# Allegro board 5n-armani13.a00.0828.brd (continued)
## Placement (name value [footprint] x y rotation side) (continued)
CON5700  USB_CON_24P  [A_USB_24P_12HOLD_RA_FOX]  7.72 87 90 bottom
CON7600  WTOB_CON_7P  [TX_WTOB_7P_49_2HD_RA_ACES]  37.83 105.3 0 bottom
D1800  CH751H-40AGP  [TX_SOD323_H39]  62.43 9.98 90 bottom
D2300  1PS79SB30  [VX_SOD523_1D7]  41.17 22.38 0 top
D2400  CH751H-40AGP  [TX_SOD323_H39]  15.98 52.18 270 top
D2401  BAW56W  [TX_SOT323_PAN]  10.72 18.98 90 top
D2500  1PS79SB30  [TX_SOD523_1D7_H28]  84.25 20.35 0 top
D2600  AZ5425-01F  [TX_ESD_2P_33_39X24_H24]  13.06 77.32 90 top
D2900  AZ5425-01F  [TX_ESD_2P_33_39X24_H24]  15.14 69.88 0 top
D2901  AZ5425-01F  [TX_ESD_2P_33_39X24_H24]  15.14 66.19 0 top
D2902  1V/0.1A  [TX_SOT323]  17.68 67.85 180 top
D3000  BAT54C  [TX_SOT23_2D4_H43]  82.42 100 270 bottom
D3001  AZ5425-01F  [TX_ESD_2P_33_39X24_H24]  56.16 98.55 180 bottom
D3002  AZ5425-01F  [TX_ESD_2P_33_39X24_H24]  57.91 98.55 0 bottom
D3003  1PS79SB30  [VX_SOD523_1D7]  59.64 96.62 0 top
D3004  1PS79SB30  [VX_SOD523_1D7]  59.64 98.81 0 top
D3600  1PS79SB30  [TX_SOD523_1D7_H28]  204.62 67.34 270 bottom
D3601  AZ5725-01F  [TX_ESD_2P_33_39X24_COLAY]  134.49 18.27 0 bottom
D3602  AZ5725-01F  [TX_ESD_2P_33_39X24_COLAY]  136.77 18.27 0 bottom
D3603  AZ5725-01F  [TX_ESD_2P_33_39X24_COLAY]  140.08 18.52 0 bottom
D3604  1PS79SB30  [TX_SOD523_1D7_H28]  99.59 83.95 180 top
D3605  1PS79SB30  [TX_SOD523_1D7_H28]  59.97 23.98 0 top
D3700  CH751H-40AGP  [TX_SOD323_H39]  131.55 93.88 0 bottom
D3800  AZ5425-01F  [TX_ESD_2P_33_39X24_H24]  4.32 37.21 90 bottom
D3801  AZ5425-01F  [TX_ESD_2P_33_39X24_H24]  4.06 54 270 bottom
D3802  AZ5425-01F  [TX_ESD_2P_33_39X24_H24]  14.93 52.24 180 bottom
D3803  AZ5425-01F  [TX_ESD_2P_33_39X24_H24]  10.9 55.1 270 bottom
D3804  AZ5725-01F  [TX_ESD_2P_33_39X24_COLAY]  19.1 36.5 180 bottom
D3805  BAT54C  [TX_SOT23_2D4_H43]  49.4 13.16 270 bottom
D3806  AZ5425-01F  [TX_ESD_2P_33_39X24_H24]  15.7 39.45 0 bottom
D3807  BAT54AW  [TX_SOT323]  21.01 38.97 180 bottom
D5100  AZ5425-01F  [TX_ESD_2P_33_39X24_H24]  50.83 10.57 90 top
D5101  AZ5425-01F  [TX_ESD_2P_33_39X24_H24]  53.24 10.57 90 top
D5102  AZ5425-01F  [TX_ESD_2P_33_39X24_H24]  56.54 10.57 90 top
D5103  AZ5425-01F  [TX_ESD_2P_33_39X24_H24]  57.81 10.57 90 top
D5700  AZ5425-01F  [TX_ESD_2P_33_39X24_H24]  12.24 82.3 270 bottom
D5701  AZ5425-01F  [TX_ESD_2P_33_39X24_H24]  12.24 84.05 90 bottom
D5702  AZ5425-01F  [TX_ESD_2P_33_39X24_H24]  11.46 89.49 90 top
D5703  AZ5425-01F  [TX_ESD_2P_33_39X24_H24]  11.46 87.4 270 top
D5704  AZ5425-01F  [TX_ESD_2P_33_39X24_H24]  13.41 86.59 180 top
D5705  AZ5425-01F  [TX_ESD_2P_33_39X24_H24]  13.06 80.8 180 bottom
D5706  AZ5425-01F  [TX_ESD_2P_33_39X24_H24]  13.06 79.43 180 bottom
D5707  AZ5425-01F  [TX_ESD_2P_33_39X24_H24]  11.4 92.2 270 top
D5708  ESD5401N-2/TR  [TX_DFN1006_2P_43X28_WIL]  12.32 90.85 0 bottom
D5709  ESD5401N-2/TR  [TX_DFN1006_2P_43X28_WIL]  12.32 89.22 0 bottom
D5800  BAT54C  [TX_SOT23_2D4_H43]  19.96 75.24 270 bottom
F2600  0.75A/6V  [TX_POLYSWITCH_2P_87X59]  19.15 73.15 0 top
F3000  1.5A/24V  [TX_POLYSWITCH_2P_1812_H71]  76.66 104.22 90 bottom
F5100  0.5A/6V  [TX_POLYSWITCH_0603_71X39]  175.51 19.76 0 bottom
H5200  O118X98DO118X98N  [HOLE_O118X98DO118X98N]  217.33 24.8 0 top
H5201  CT236CB173D157  [NB_H_CT236CB173D157_P2_S]  99.93 71.05 0 top
H5202  CT236CB173D157  [NB_H_CT236CB173D157_P2_S]  99.93 37.05 0 top
H5203  C98D98N  [A_HOLE_C98D98N]  6.83 24.8 180 top
H5204  S232D87  [NB_H_S232D87_P2_S]  7.68 76.85 0 top
H5205  CT236CB173D157  [NB_H_CT236CB173D157_P2_S]  133.93 37.05 0 top
H5207  C315D169  [NB_H_C315D169_P2_S]  208.63 13.3 180 bottom
H5208  C315D169  [NB_H_C315D169_P2_S]  168.43 33.6 0 top
H5209  ST252CB315D205  [NB_H_ST252CB315D205_P2_S]  6.83 32.1 0 top
H5210  CT236CB173D157  [NB_H_CT236CB173D157_P2_S]  179.53 108.7 90 top
H5211  C315D169  [NB_H_C315D169_P2_S]  98.88 7 180 bottom
H5212  CT236CB173D157  [NB_H_CT236CB173D157_P2_S]  171.43 65.3 0 top
H5213  CT236CB173D157  [NB_H_CT236CB173D157_P2_S]  137.23 93.3 0 top
H5214  ST295CB315D169  [NB_H_ST295CB315D169_P2_S]  122.93 95.2 0 top
H5215  S209D98  [NB_H_S209D98_P2_S]  5.68 97.2 180 bottom
H5216  CT236CB173D157  [NB_H_CT236CB173D157_P2_S]  133.93 71.05 0 top
J3800  AUDIO_JACK_6P  [TX_AUDIO_JACK_6P_TECHK]  0.98 47.4 90 bottom
J5300  FPC_CON_12P  [TX_FPC_12P_20_2HD_RA_PANA]  89 4.54 0 top
J5301  FPC_CON_12P  [TX_FPC_12P_20_2HD_RA_PANA]  44.1 63.32 90 top
L2600  90ohm  [TX_CHOKE_4P_49X39_MURA]  16.82 64.65 0 bottom
L2601  90ohm  [TX_CHOKE_4P_49X39_MURA]  16.79 62.54 0 bottom
L2602  90ohm  [TX_CHOKE_4P_49X39_MURA]  16.79 60.23 0 bottom
L2603  90ohm  [TX_CHOKE_4P_49X39_MURA]  16.79 66.93 0 bottom
L3000  90ohm  [CHOKE_4P_49X39_MURA]  53.34 98.53 180 bottom
L3601  70Ohm/100Mhz  [TX_L0603_T015]  129.11 18.85 270 bottom
L3602  70Ohm/100Mhz  [TX_L0603_T015]  130.74 18.87 270 bottom
L3603  70Ohm/100Mhz  [TX_L0603_T015]  132.46 18.87 270 bottom
L3800  70Ohm/100Mhz  [TX_L0603_T015]  19.19 22.07 180 top
L3801  11Ohm/100Mhz  [TX_L0603_T02_H37]  14.13 47.94 90 bottom
L3802  11Ohm/100Mhz  [TX_L0603_T02_H37]  6.83 53.69 180 bottom
L3803  11Ohm/100Mhz  [TX_L0603_T02_H37]  13.53 53.71 180 bottom
L3804  11Ohm/100Mhz  [TX_L0603_T02_H37]  5.93 40.82 180 bottom
L3805  70Ohm/100Mhz  [TX_L0603_T015]  20.45 36.25 180 top
L3806  70Ohm/100Mhz  [TX_L0603_T015]  15.58 37.35 180 bottom
L5700  90ohm  [TX_CHOKE_4P_49X39_MURA]  14.63 83.04 90 bottom
L5701  90ohm  [TX_CHOKE_4P_49X39_MURA]  13.51 88.27 180 top
L5702  90ohm  [TX_CHOKE_4P_49X39_MURA]  17.83 85.47 0 top
L5703  90ohm  [TX_CHOKE_4P_49X39_MURA]  17.37 78.74 0 top
L5704  90ohm  [TX_CHOKE_4P_49X39_MURA]  18.29 83.34 0 top
L5705  90ohm  [TX_CHOKE_4P_49X39_MURA]  21.79 81.46 0 top
L6700  120ohm  [TX_L0402_T02]  150.07 90.58 180 top
L6701  120ohm  [TX_L0402_T02]  155.63 107.79 270 top
L6702  220Ohm  [TX_L0402]  168.88 82.55 180 top
LED5000  WHITE/YELLOW  [TX_LED_3P_126X59_CO]  1.25 99.01 90 bottom
NOREF  -  []  57.53 26.82 90 top
NOREF#2  -  []  198.96 58.41 90 top
NOREF#3  -  []  78.18 92.75 90 top
NOREF#4  -  []  2.55 55.6 90 top
NOREF#5  -  []  1.31 53.83 90 top
NOREF#6  -  [unnamed#2]  204.29 101.22 0 top
NOREF#7  -  []  53.43 25.55 90 top
NOREF#8  -  []  1.31 55.27 0 top
NOREF#9  -  []  1.25 97.51 90 top
NOREF#10  -  []  62.99 -27.18 0 top
NOREF#11  -  []  194.06 46.89 0 top
NOREF#12  -  []  62.08 25.57 90 top
NOREF#13  -  []  199.9 57.86 0 top
NOREF#14  -  []  76.13 40.3 0 top
NOREF#15  -  []  62.08 56.57 90 top
NOREF#16  -  [unnamed#2]  26.09 9.58 0 top
NOREF#17  -  []  53.43 25.55 90 top
NOREF#18  -  []  66.18 24.55 90 top
NOREF#19  -  []  53.43 25.55 90 top
NOREF#20  -  []  83.05 39.34 0 top
NOREF#21  -  [unnamed#2]  204.76 21.72 0 top
NOREF#22  -  []  220.27 77.35 270 top
NOREF#23  -  []  198.96 58.41 0 top
NOREF#24  -  []  198.75 57.66 0 top
NOREF#25  -  []  78.18 25.15 90 top
NOREF#26  -  []  198.75 57.66 90 top
NOREF#27  -  []  1.25 55.6 0 top
NOREF#28  -  [unnamed#2]  203.58 102.36 180 bottom
NOREF#29  -  []  275.44 53.76 180 bottom
NOREF#30  -  []  90.2 84.72 0 bottom
NOREF#31  -  [unnamed#2]  212.52 22.48 180 bottom
NOREF#32  -  [unnamed#2]  33.93 5.87 180 bottom
PC7600  0.1uF/50V  [TX_C0402_H22]  57.68 109.07 90 top
PC7601  1UF/50V  [TX_C0603]  43.49 100.13 180 bottom
PC7602  100PF/50V  [TX_C0402]  55.47 109.12 90 top
PC7603  0.022UF/16V  [TX_C0402]  35.59 89.51 90 top
PC7604  0.1UF/16V  [TX_C0402]  68.86 97.59 270 top
PC7605  10UF/25V  [TX_C0805_T02_H57]  30.61 97.74 90 bottom
PC7606  0.1UF/50V  [TX_C0603_T015_H37]  58.83 109.07 90 top
PC7607  0.1UF/50V  [TX_C0603_T015_H37]  40.95 100.03 180 top
PC7608  100PF/50V  [TX_C0402]  20.14 57.69 180 bottom
PC7609  1UF/50V  [TX_C0603]  30.38 100.84 180 top
PC7610  100PF/50V  [TX_C0402]  38.25 101.85 0 top
PC7611  0.1UF/50V  [TX_C0603_T015_H37]  36.51 97.48 0 top
PC7612  0.1UF/50V  [TX_C0603_T015_H37]  37.29 99.29 270 top
PC7700  10UF/25V  [TX_C0805_T02_H57]  187.73 23.9 0 bottom
PC7701  10UF/25V  [TX_C0805_T02_H57]  187.73 27.47 0 bottom
PC7702  10UF/25V  [TX_C0805_T02_H57]  187.73 25.68 0 bottom
PC7703  10UF/25V  [TX_C0805_T02_H57]  187.73 22.11 0 bottom
PC7704  10UF/25V  [TX_C0805_T02_H57]  160.88 28.15 270 bottom
PC7705  10UF/25V  [TX_C0805_T02_H57]  162.71 32.79 90 bottom
PC7706  10UF/25V  [TX_C0805_T02_H57]  159.06 28.27 270 bottom
PC7707  10UF/25V  [TX_C0805_T02_H57]  156.64 26.75 270 bottom
PC7708  4.7UF/6.3V  [TX_C0402_T02_H26]  192.28 26.9 90 bottom
PC7709  1UF/25V  [TX_C0603_T015_H37]  190.5 27.62 90 bottom
PC7710  1UF/25V  [TX_C0603_T015_H37]  190.39 25.35 270 bottom
PC7711  0.22UF/25V  [TX_C0603]  192.41 24.95 90 bottom
PC7712  1UF/25V  [TX_C0603_T015_H37]  192.71 29.34 180 bottom
PC7713  4.7UF/6.3V  [TX_C0402_T02_H26]  194.36 29.49 90 bottom
PC7714  4.7UF/6.3V  [TX_C0402_T02_H26]  192.62 22.18 270 bottom
PC7715  0.22UF/25V  [TX_C0603]  194.6 22.26 180 bottom
PC7716  0.1UF/25V  [TX_C0402]  195.35 29.49 90 bottom
PC7717  1UF/25V  [TX_C0603_T015_H37]  200.81 21.41 0 bottom
PC7718  1UF/6.3V  [TX_C0402]  198.72 22.35 90 bottom
PC7719  0.22UF/25V  [TX_C0603]  200.81 22.71 0 bottom
PC7720  10UF/25V  [TX_C0805_T02_H57]  154 24.16 0 bottom
PC7721  10PF/50V  [TX_C0402]  200.71 29.36 0 bottom
PC7722  4700PF/50V  [TX_C0402]  150.18 23.32 270 bottom
PC7723  22nF/50V  [TX_C0402]  202.36 26.37 0 bottom
PC7800  0.022UF/16V  [TX_C0402]  176.54 53.83 180 bottom
PC7801  1UF/16V  [TX_C0402]  170.33 48.57 180 bottom
PC7802  4.7UF/10V  [TX_C0603]  168.05 48.63 90 bottom
PC7803  0.1UF/16V  [TX_C0402]  176.53 54.75 0 bottom
PC7804  0.22UF/25V  [TX_C0603]  170.33 47.12 0 bottom
PC7805  2200PF/50V  [TX_C0402]  176.72 52.78 0 bottom
PC7806  0.1UF/16V  [TX_C0402]  178.59 54.66 180 bottom
PC7807  0.022UF/16V  [TX_C0402]  177.55 53.18 90 top
PC7808  0.022UF/16V  [TX_C0402]  176.61 53.14 90 top
PC7809  0.068UF/16V  [TX_C0402]  180.11 46.66 0 top
PC7810  0.027UF/25V  [TX_C0402_H22]  180.11 47.6 0 top
PC7811  2200PF/50V  [TX_C0402]  179.1 44.6 270 top
PC7812  33PF/50V  [TX_C0402]  173.25 53.32 270 bottom
PC7813  0.1UF/16V  [TX_C0402]  179.1 42.95 270 top
PC7814  68PF/50V  [TX_C0402]  179.35 49.38 0 bottom
PC7815  2200PF/50V  [TX_C0402]  173.47 57.13 180 bottom
PC7816  6800PF/25V  [TX_C0402]  181.1 50.29 180 bottom
PC7817  220PF/50V  [TX_C0402]  176.15 59.21 180 bottom
PC7818  1000PF/50V  [TX_C0402]  178.77 47.35 90 bottom
PC7819  1000PF/50V  [TX_C0402]  174.98 55.48 270 top
PC7820  330PF/50V  [TX_C0402]  174.75 55.58 90 bottom
PC7821  1000PF/50V  [TX_C0402]  180.19 50.07 180 top
PC7822  680PF/50V  [TX_C0402]  181.43 48.88 90 bottom
PC7823  10NF/25V  [TX_C0402]  175.26 53.33 90 bottom
PC7824  330PF/50V  [TX_C0402]  172.29 53.95 180 top
PC7825  330PF/50V  [TX_C0402]  176.71 49.76 0 top
PC7826  10NF/25V  [TX_C0402]  180.11 48.54 0 top
PC7827  0.047UF/16V  [TX_C0402]  167.22 46.28 90 top
PC7828  0.012UF/25V  [TX_C0402_H22]  168.15 46.28 90 top
PC7829  0.1UF/16V  [TX_C0402]  165 46.48 180 top
PC7830  2200PF/50V  [TX_C0402]  171.81 44.17 270 top
PC7831  33PF/50V  [TX_C0402]  175.95 44.6 270 bottom
PC7832  6800PF/25V  [TX_C0402]  177.75 42.55 0 top
PC7833  1000PF/50V  [TX_C0402]  170.87 44.33 90 bottom
PC7834  1000PF/50V  [TX_C0402]  175.03 44.6 270 bottom
PC7835  330PF/50V  [TX_C0402]  177.32 44.6 90 bottom
PC7836  0.1UF/16V  [TX_C0402]  167.97 49.46 0 top
PC7837  10NF/25V  [TX_C0402]  172.75 43.97 270 bottom
PC7838  100PF/50V  [TX_C0402]  173.63 42.7 180 bottom
PC7839  22nF/50V  [TX_C0402]  178.82 56.54 270 bottom
PC7840  0.068UF/16V  [TX_C0402]  177.88 56.54 270 bottom
PC7841  330PF/50V  [TX_C0402]  174.85 57.67 270 bottom
PC7900  4.7UF/10V  [TX_C0402_T02_H26]  159.03 41.91 180 bottom
PC7901  10UF/25V  [TX_C0805_T02_H57]  153.32 44.2 180 bottom
PC7902  10UF/25V  [TX_C0805_T02_H57]  153.32 42.42 180 bottom
PC7903  1000PF/50V  [TX_C0402]  156.34 49.3 270 bottom
PC7904  0.22UF/25V  [TX_C0603]  157.79 45.19 270 bottom
PC7905  1000PF/50V  [TX_C0402]  149.51 44.4 0 bottom
PC7906  10UF/25V  [TX_C0805_T02_H57]  156.31 53.04 90 bottom
PC7907  10UF/25V  [TX_C0805_T02_H57]  152.32 58.37 180 bottom
PC7908  10UF/25V  [TX_C0805_T02_H57]  152.32 56.57 180 bottom
PC7909  4.7UF/10V  [TX_C0402_T02_H26]  161.27 52.15 0 bottom
PC7910  1000PF/50V  [TX_C0402]  156.47 63.07 270 bottom
PC7911  0.22UF/25V  [TX_C0603]  157.84 54.74 270 bottom
PC7912  1000PF/50V  [TX_C0402]  149.96 58.73 0 bottom
PC7913  10UF/25V  [TX_C0805_T02_H57]  156.46 43.16 0 bottom
PC7914  1000PF/50V  [TX_C0402]  150.88 49.81 0 top
PC7915  1000PF/50V  [TX_C0402]  148.41 64.11 0 top
PC8000  0.22UF/25V  [TX_C0603]  147.75 31.75 180 bottom
PC8001  10UF/25V  [TX_C0805_T02_H57]  156.36 35.74 180 bottom
PC8002  4.7UF/10V  [TX_C0402_T02_H26]  142.98 28.73 180 bottom
PC8003  10UF/25V  [TX_C0805_T02_H57]  156.36 37.54 180 bottom
PC8004  1000PF/50V  [TX_C0402]  149.66 39.12 180 top
PC8005  1000PF/50V  [TX_C0402]  152.1 34.62 0 bottom
PC8006  4.7UF/10V  [TX_C0402_T02_H26]  161.82 62.33 0 bottom
PC8007  10UF/25V  [TX_C0805_T02_H57]  156.44 66.47 0 bottom
PC8008  10UF/25V  [TX_C0805_T02_H57]  152.81 67.87 180 bottom
PC8009  10UF/25V  [TX_C0805_T02_H57]  152.81 66.09 180 bottom
PC8010  1000PF/50V  [TX_C0402]  155.91 73.36 270 bottom
PC8011  0.22UF/25V  [TX_C0603]  158.51 65.1 270 bottom
PC8012  1000PF/50V  [TX_C0402]  148.92 71.55 0 top
PC8013  1000PF/50V  [TX_C0402]  149.89 72.8 0 top
PC8100  22UF/6.3V  [TX_C0603_T02_H39]  122.81 57.48 90 top
PC8101  22UF/6.3V  [TX_C0603_T02_H39]  115.47 57.55 90 top
PC8102  22UF/6.3V  [TX_C0603_T02_H39]  126.49 56.54 270 top
PC8103  22UF/6.3V  [TX_C0603_T02_H39]  126.67 58.87 90 top
PC8104  22UF/6.3V  [TX_C0603_T02_H39]  116.82 57.55 90 top
PC8105  22UF/6.3V  [TX_C0603_T02_H39]  138.63 55.76 270 bottom
PC8106  22UF/6.3V  [TX_C0603_T02_H39]  138.63 43.89 270 bottom
PC8107  22UF/6.3V  [TX_C0603_T02_H39]  119.04 54.89 270 top
PC8108  22UF/6.3V  [TX_C0603_T02_H39]  117.68 54.89 270 top
PC8109  22UF/6.3V  [TX_C0603_T02_H39]  116.28 54.89 270 top
PC8110  22UF/6.3V  [TX_C0603_T02_H39]  114.95 54.89 270 top
PC8111  22UF/6.3V  [TX_C0603_T02_H39]  143.79 36.96 0 top
PC8112  22UF/6.3V  [TX_C0603_T02_H39]  143.79 35.59 0 top
PC8113  22UF/6.3V  [TX_C0603_T02_H39]  143.66 34.19 0 top
PC8114  22UF/6.3V  [TX_C0603_T02_H39]  141.45 34.39 270 top
PC8115  22UF/6.3V  [TX_C0603_T02_H39]  143.79 38.31 0 top
PC8116  22UF/6.3V  [TX_C0603_T02_H39]  143.43 40.13 90 top
PC8117  22UF/6.3V  [TX_C0603_T02_H39]  142.04 40.41 90 top
PC8118  22UF/6.3V  [TX_C0603_T02_H39]  127.82 56.54 270 top
PC8119  22UF/6.3V  [TX_C0603_T02_H39]  117.58 52.22 90 top
PC8120  22UF/6.3V  [TX_C0603_T02_H39]  116.23 52.22 90 top
PC8121  22UF/6.3V  [TX_C0603_T02_H39]  114.89 52.22 90 top
PC8122  22UF/6.3V  [TX_C0603_T02_H39]  126.57 54.26 270 top
PC8123  22UF/6.3V  [TX_C0603_T02_H39]  138.79 65.33 90 bottom
PC8124  22UF/6.3V  [TX_C0603_T02_H39]  118.93 52.22 90 top
PC8125  22UF/6.3V  [TX_C0603_T02_H39]  116.26 49.56 270 top
PC8126  22UF/6.3V  [TX_C0603_T02_H39]  120.25 49.56 270 top
PC8127  22UF/6.3V  [TX_C0603_T02_H39]  118.93 49.56 270 top
PC8128  22UF/6.3V  [TX_C0603_T02_H39]  143.72 43.36 0 top
PC8129  22UF/6.3V  [TX_C0603_T02_H39]  114.91 49.56 270 top
PC8130  22UF/6.3V  [TX_C0603_T02_H39]  141.92 43.11 270 top
PC8131  22UF/6.3V  [TX_C0603_T02_H39]  140.6 43.11 270 top
PC8132  22UF/6.3V  [TX_C0603_T02_H39]  143.97 44.73 0 top
PC8133  22UF/6.3V  [TX_C0603_T02_H39]  117.59 49.56 270 top
PC8134  22UF/6.3V  [TX_C0603_T02_H39]  113.59 49.56 270 top
PC8135  22UF/6.3V  [TX_C0603_T02_H39]  118.16 57.55 90 top
PC8136  22UF/6.3V  [TX_C0603_T02_H39]  143.97 46.08 0 top
PC8137  22UF/6.3V  [TX_C0603_T02_H39]  118.21 63.4 90 top
PC8138  22UF/6.3V  [TX_C0603_T02_H39]  116.87 63.4 90 top
PC8139  22UF/6.3V  [TX_C0603_T02_H39]  115.52 63.4 90 top
PC8140  22UF/6.3V  [TX_C0603_T02_H39]  115.57 83.7 180 bottom
PC8141  22UF/6.3V  [TX_C0603_T02_H39]  124.08 77.5 0 top
PC8142  22UF/6.3V  [TX_C0603_T02_H39]  118.21 60.16 270 top
PC8143  22UF/6.3V  [TX_C0603_T02_H39]  115.47 60.16 270 top
PC8144  22UF/6.3V  [TX_C0603_T02_H39]  114.18 63.4 90 top
PC8145  22UF/6.3V  [TX_C0603_T02_H39]  111.54 64.19 180 top
PC8146  22UF/6.3V  [TX_C0603_T02_H39]  111.53 62.33 180 top
PC8147  22UF/6.3V  [TX_C0603_T02_H39]  127.58 80.22 270 bottom
PC8148  22UF/6.3V  [TX_C0603_T02_H39]  121.29 78.84 180 bottom
PC8149  22UF/6.3V  [TX_C0603_T02_H39]  124.08 77.5 0 bottom
PC8150  22UF/6.3V  [TX_C0603_T02_H39]  116.87 60.16 270 top
PC8151  22UF/6.3V  [TX_C0603_T02_H39]  128.96 80.22 270 bottom
PC8152  22UF/6.3V  [TX_C0603_T02_H39]  121.62 84.86 90 bottom
PC8153  22UF/6.3V  [TX_C0603_T02_H39]  114.12 60.16 270 top
PC8154  22UF/6.3V  [TX_C0603_T02_H39]  111.32 60.96 180 top
PC8155  22UF/6.3V  [TX_C0603_T02_H39]  111.73 79.96 0 top
PC8156  22UF/6.3V  [TX_C0603_T02_H39]  124.05 80.27 0 bottom
PC8157  22UF/6.3V  [TX_C0603_T02_H39]  120.48 46.94 90 top
PC8158  22UF/6.3V  [TX_C0603_T02_H39]  127.03 50 90 top
PC8159  22UF/6.3V  [TX_C0603_T02_H39]  119.08 46.94 90 top
PC8160  22UF/6.3V  [TX_C0603_T02_H39]  128.4 50 90 top
PC8161  22UF/6.3V  [TX_C0603_T02_H39]  140.08 34.78 270 top
PC8162  22UF/6.3V  [TX_C0603_T02_H39]  140.39 34.78 270 bottom
PC8163  22UF/6.3V  [TX_C0603_T02_H39]  121.29 80.22 180 top
PC8164  22UF/6.3V  [TX_C0603_T02_H39]  115.55 85.09 180 bottom
PC8165  22UF/6.3V  [TX_C0603_T02_H39]  111.76 81.31 0 top
PC8166  22UF/6.3V  [TX_C0603_T02_H39]  121.29 80.22 180 bottom
PC8167  22UF/6.3V  [TX_C0603_T02_H39]  126.16 80.22 270 bottom
PC8168  22UF/6.3V  [TX_C0603_T02_H39]  119.02 87.25 90 top
PC8169  22UF/6.3V  [TX_C0603_T02_H39]  124.08 80.27 0 top
PC8170  22UF/6.3V  [TX_C0603_T02_H39]  124.56 87.25 90 top
PC8171  22UF/6.3V  [TX_C0603_T02_H39]  123.19 87.25 90 top
PC8172  22UF/6.3V  [TX_C0603_T02_H39]  121.29 77.5 180 top
PC8173  22UF/6.3V  [TX_C0603_T02_H39]  129.82 87.25 90 top
PC8174  22UF/6.3V  [TX_C0603_T02_H39]  128.42 87.25 90 top
PC8175  22UF/6.3V  [TX_C0603_T02_H39]  121.29 78.84 180 top
PC8176  22UF/6.3V  [TX_C0603_T02_H39]  121.29 77.5 180 bottom
PC8177  22UF/6.3V  [TX_C0603_T02_H39]  124.08 78.89 0 bottom
PC8178  22UF/6.3V  [TX_C0603_T02_H39]  139.27 43.11 270 top
PC8179  22UF/6.3V  [TX_C0603_T02_H39]  114.12 57.55 90 top
PC8180  22UF/6.3V  [TX_C0603_T02_H39]  144.78 47.42 0 top
PC8181  22UF/6.3V  [TX_C0603_T02_H39]  144.78 48.82 0 top
PC8182  22UF/6.3V  [TX_C0603_T02_H39]  144.78 50.22 0 top
PC8183  22UF/6.3V  [TX_C0603_T02_H39]  124.08 78.89 0 top
PC8184  22UF/6.3V  [TX_C0603_T02_H39]  115.57 82.3 180 bottom
PC8185  22UF/6.3V  [TX_C0603_T02_H39]  120.42 87.25 90 top
PC8186  22UF/6.3V  [TX_C0603_T02_H39]  121.82 87.25 90 top
PC8187  22UF/6.3V  [TX_C0603_T02_H39]  119.13 84.86 90 bottom
PC8600  1UF/16V  [TX_C0402]  101.12 100.99 90 top
PC8601  0.1UF/25V  [TX_C0402]  97.13 99.34 180 top
PC8602  10UF/25V  [TX_C0805_T02_H57]  82.42 104.27 0 bottom
PC8603  10UF/25V  [TX_C0805_T02_H57]  82.42 102.49 0 bottom
PC8604  330PF/50V  [TX_C0402]  83.06 104.47 0 top
PC8605  1000PF/50V  [TX_C0402]  103.84 96.24 270 top
PC8606  1000PF/50V  [TX_C0402]  83.69 111.1 180 bottom
PC8607  680PF/50V  [TX_C0402]  83.69 110.16 180 bottom
PC8608  10UF/6.3V  [TX_C0402_T02_H28]  93.19 108.64 90 bottom
PC8609  1UF/6.3V  [TX_C0402]  104.29 99.49 0 top
PC8610  330PF/50V  [TX_C0402]  82.4 108.77 180 top
PC8611  56PF/50V  [TX_C0402]  102.87 94.41 90 top
PC8612  0.1UF/16V  [TX_C0402]  104.17 94.06 0 top
PC8613  10UF/6.3V  [TX_C0402_T02_H28]  96.32 95.71 180 top
PC8614  10UF/6.3V  [TX_C0402_T02_H28]  97.94 95.15 180 top
PC8615  10UF/6.3V  [TX_C0402_T02_H28]  97.94 94.13 180 top
PC8616  0.033UF/16V  [TX_C0402]  100.84 94.03 270 top
PC8617  22UF/6.3V  [TX_C0603_T02_H39]  98.3 97.49 0 bottom
PC8618  22UF/6.3V  [TX_C0603_T02_H39]  98.91 103.01 0 bottom
PC8619  22UF/6.3V  [TX_C0603_T02_H39]  98.29 100.26 0 bottom
PC8620  22UF/6.3V  [TX_C0603_T02_H39]  98.91 101.64 0 bottom
PC8621  1500PF/50V  [TX_C0402]  107.65 98.02 90 top
PC8622  10PF/50V  [TX_C0402]  80.14 103.89 0 bottom
PC8700  10UF/25V  [TX_C0805_T02_H57]  178.23 35.28 270 bottom
PC8701  22UF/6.3V  [TX_C0603_T02_H39]  174.27 31.45 270 bottom
PC8702  22UF/6.3V  [TX_C0603_T02_H39]  163.86 45.87 180 bottom
PC8703  22UF/6.3V  [TX_C0603_T02_H39]  163.86 47.22 180 bottom
PC8704  220PF/50V  [TX_C0402]  174.14 29.47 0 bottom
PC8705  1UF/16V  [TX_C0402]  176.35 33.12 270 bottom
PC8706  1500PF/50V  [TX_C0402]  172.36 38.67 270 bottom
PC8707  22UF/6.3V  [TX_C0603_T02_H39]  162.05 50.47 270 bottom
PC8708  22UF/6.3V  [TX_C0603_T02_H39]  166.17 46.21 0 bottom
PC8709  0.22UF/25V  [TX_C0603]  170.54 40.82 90 bottom
PC8710  22UF/6.3V  [TX_C0603_T02_H39]  174.75 33.26 0 bottom
PC8711  22UF/6.3V  [TX_C0603_T02_H39]  166.27 48.85 0 bottom
PC8712  22UF/6.3V  [TX_C0603_T02_H39]  163.86 48.57 180 bottom
PC8713  0.1UF/25V  [TX_C0402]  176.15 39 0 bottom
PC8714  10UF/25V  [TX_C0805_T02_H57]  180.04 35.28 270 bottom
PC8715  10PF/50V  [TX_C0402]  181.41 35.64 90 bottom
PC8800  10UF/25V  [TX_C0805_T02_H57]  44.04 19.13 90 bottom
PC8801  1UF/16V  [TX_C0402]  40.74 19.69 180 top
PC8802  1000PF/25V  [TX_C0402]  40.87 15.76 0 top
PC8803  22PF/50V  [TX_C0402]  41.2 18 90 top
PC8804  22UF/6.3V  [TX_C0603_T02_H39]  51.26 20.63 90 bottom
PC8805  22UF/6.3V  [TX_C0603_T02_H39]  49.91 20.63 90 bottom
PC8806  22UF/6.3V  [TX_C0603_T02_H39]  48.23 16.44 270 bottom
PC8807  22UF/6.3V  [TX_C0603_T02_H39]  99.33 111 270 bottom
PC8808  330PF/50V  [TX_C0402]  107.04 114.3 180 bottom
PC8809  22UF/6.3V  [TX_C0603_T02_H39]  98.65 113.64 90 bottom
PC8810  22PF/50V  [TX_C0402]  110.82 112.98 0 top
PC8811  1000PF/25V  [TX_C0402]  107.42 114.25 180 top
PC8812  1UF/16V  [TX_C0402]  111.23 112.8 90 bottom
PC8813  10UF/25V  [TX_C0805_T02_H57]  112.14 111.08 0 bottom
PC8814  0.1UF/16V  [TX_C0402]  45.09 13.54 180 top
PC8900  0.1UF/25V  [TX_C0402]  196.11 58.27 0 bottom
PC8901  0.1UF/25V  [TX_C0402]  199.09 62.64 90 bottom
PC8902  1UF/16V  [TX_C0402]  200.48 62.64 90 bottom
PC8903  1UF/16V  [TX_C0402]  200.28 55.82 270 bottom
PC8904  0.1UF/25V  [TX_C0402]  204.92 59.92 180 bottom
PC8905  10UF/25V  [TX_C0805_T02_H57]  179.03 41.76 90 bottom
PC8906  10UF/25V  [TX_C0805_T02_H57]  177.25 41.77 90 bottom
PC8907  1000PF/50V  [TX_C0402]  186.61 41.1 90 bottom
PC8908  1000PF/50V  [TX_C0402]  185.8 47.22 90 bottom
PC8909  10UF/6.3V  [TX_C0402_T02_H28]  201.96 38.25 0 bottom
PC8910  1000PF/50V  [TX_C0402]  183.63 44.67 180 bottom
PC8911  0.1UF/16V  [TX_C0402]  202.03 63.14 90 bottom
PC8912  56PF/50V  [TX_C0402]  201.21 55.82 90 bottom
PC8913  0.1UF/16V  [TX_C0402]  204.8 55.69 90 bottom
PC8914  10UF/25V  [TX_C0805_T02_H57]  190.68 50.6 270 bottom
PC8915  10UF/25V  [TX_C0805_T02_H57]  188.77 50.6 270 bottom
PC8916  1000PF/50V  [TX_C0402]  193.9 52.73 90 bottom
PC8917  0.1UF/16V  [TX_C0402]  203.51 57.61 0 bottom
PC8918  1000PF/50V  [TX_C0402]  191.54 60.86 180 bottom
PC8919  10UF/6.3V  [TX_C0402_T02_H28]  178.11 58.83 180 bottom
PC8920  1000PF/50V  [TX_C0402]  193.68 55.81 270 bottom
PC8921  0.1UF/16V  [TX_C0402]  201.65 59.18 90 top
PC8922  56PF/50V  [TX_C0402]  199.35 55.83 90 bottom
PC8923  0.1UF/16V  [TX_C0402]  197 55.6 180 bottom
PC8924  10UF/25V  [TX_C0805_T02_H57]  175.47 41.77 90 bottom
PC8925  10UF/25V  [TX_C0805_T02_H57]  180.81 41.76 90 bottom
PC9000  1UF/16V  [TX_C0402]  36.4 72.62 180 top
PC9001  1UF/16V  [TX_C0402]  39.27 70.13 0 top
PC9002  2200PF/50V  [TX_C0402]  32.77 69.76 180 top
PC9003  1UF/16V  [TX_C0402]  35.13 67.64 0 top
PC9004  1UF/16V  [TX_C0402]  36.75 67.64 180 top
PC9005  1UF/16V  [TX_C0402]  46.84 69.85 180 top
PC9007  1000PF/25V  [TX_C0402]  33.1 70.69 180 top
PC9100  1UF/16V  [TX_C0402]  182.19 13.34 90 bottom
PC9101  1UF/16V  [TX_C0402]  180.02 11.61 270 bottom
PC9102  2200PF/50V  [TX_C0402]  179.71 17 90 bottom
PC9103  1UF/16V  [TX_C0402]  182.19 14.94 270 bottom
PC9104  1UF/16V  [TX_C0402]  177.14 12.79 90 bottom
PC9105  1000PF/25V  [TX_C0402]  178.77 17 90 bottom
PC9107  1UF/16V  [TX_C0402]  198.78 54.05 0 bottom
PC9108  1000PF/25V  [TX_C0402]  202.49 52.94 0 bottom
PC9109  1UF/16V  [TX_C0402]  200.43 54.05 180 bottom
PC9110  1UF/16V  [TX_C0402]  196.37 49.89 180 bottom
PC9111  1UF/16V  [TX_C0402]  196.37 52.63 180 bottom
PC9112  1000PF/25V  [TX_C0402]  202.49 52 0 bottom
PC9113  1UF/16V  [TX_C0402]  202.49 51.06 0 bottom
PC9114  1UF/16V  [TX_C0402]  177.06 14.89 270 bottom
PC9200  1UF/16V  [TX_C0402]  140.92 22.13 270 bottom
PC9201  2200PF/50V  [TX_C0402]  135.69 24.33 180 bottom
PC9202  1UF/16V  [TX_C0402]  137.77 21.29 0 bottom
PC9203  1UF/16V  [TX_C0402]  138.2 26.27 0 bottom
PC9204  1000PF/25V  [TX_C0402]  135.69 23.4 180 bottom
PC9205  1UF/16V  [TX_C0402]  143.87 24.08 90 top
PC9206  1UF/16V  [TX_C0402]  139.83 26.27 180 bottom
PC9402  0.1UF/25V  [TX_C0402]  104.17 95.35 180 bottom
PC9403  0.1UF/25V  [TX_C0402]  113.98 106.05 270 bottom
PC9404  1UF/6.3V  [TX_C0402]  111.38 106.07 270 bottom
PC9405  2.2UF/6.3V  [TX_C0402]  107.72 101.63 0 bottom
PC9406  2.2UF/6.3V  [TX_C0402]  117.65 102.52 180 bottom
PC9407  0.1UF/25V  [TX_C0402]  117.04 101.25 270 bottom
PC9409  0.1UF/25V  [TX_C0402]  117.88 99.14 180 bottom
PC9410  0.47UF/6.3V  [TX_C0402]  108.26 94.66 270 bottom
PC9411  0.1UF/16V  [TX_C0402]  109.07 92.53 270 bottom
PC9412  0.47UF/6.3V  [TX_C0402]  111.4 96.6 180 bottom
PC9413  1000PF/50V  [TX_C0402]  114.76 104.24 0 bottom
PC9414  0.1UF/16V  [TX_C0402]  106.25 92.53 270 bottom
PC9415  68PF/50V  [TX_C0402]  113.01 96.09 0 bottom
PC9416  330PF/50V  [TX_C0402]  113.58 94.82 90 bottom
PC9417  1000PF/50V  [TX_C0402]  115.65 92.53 270 bottom
PC9418  10NF/25V  [TX_C0402]  112.83 92.53 270 bottom
PC9419  10NF/25V  [TX_C0402]  117.53 92.53 90 bottom
PC9420  0.47UF/6.3V  [TX_C0402]  104.14 102.8 0 bottom
PC9421  0.1UF/16V  [TX_C0402]  145.62 82.07 0 bottom
PC9422  0.1UF/16V  [TX_C0402]  147.24 81.13 0 bottom
PC9423  0.1UF/16V  [TX_C0402]  145.63 78.32 0 bottom
PC9424  4700PF/50V  [TX_C0402]  109.19 94.6 270 bottom
PC9425  4700PF/50V  [TX_C0402]  111.4 95.66 180 bottom
PC9500  10UF/6.3V  [TX_C0603_T02_H39]  163.86 62.08 180 bottom
PC9501  10UF/6.3V  [TX_C0603_T02_H39]  163.86 63.4 180 bottom
PC9502  0.1UF/16V  [TX_C0402]  163.55 64.54 180 bottom
PC9503  22UF/6.3V  [TX_C0603_T02_H39]  161.37 72.11 90 bottom
PC9504  22UF/6.3V  [TX_C0603_T02_H39]  163.22 71.35 0 bottom
PC9505  0.1UF/16V  [TX_C0402]  159.84 71.45 180 bottom
PC9506  1500PF/50V  [TX_C0603]  166.24 66.27 270 bottom
PC9507  0.1UF/16V  [TX_C0402]  162.53 65.27 225 top
PC9508  22PF/50V  [TX_C0402]  167.69 65.2 0 bottom
PC9509  10UF/6.3V  [TX_C0603_T02_H39]  174.1 111.81 270 bottom
PC9510  10UF/6.3V  [TX_C0603_T02_H39]  175.44 111.81 270 bottom
PC9511  0.1UF/16V  [TX_C0402]  172.95 111.97 270 bottom
PC9512  22UF/6.3V  [TX_C0603_T02_H39]  167.74 110.82 90 bottom
PC9513  22UF/6.3V  [TX_C0603_T02_H39]  166.95 106.89 270 bottom
PC9514  0.1UF/16V  [TX_C0402]  163.58 111.56 90 bottom
PC9515  1000PF/50V  [TX_C0402]  168.71 110.9 90 top
PC9516  1500PF/50V  [TX_C0603]  176.25 113.72 0 top
PC9517  22PF/50V  [TX_C0402]  166.45 113.18 270 bottom
PC9518  22UF/6.3V  [TX_C0603_T02_H39]  166.42 110.82 90 bottom
PC9600  10UF/25V  [TX_C0805_T02_H57]  125.02 102.67 90 bottom
PC9601  10UF/25V  [TX_C0805_T02_H57]  126.8 102.67 90 bottom
PC9602  820PF/50V  [TX_C0402]  128.45 96.47 270 bottom
PC9603  10UF/6.3V  [TX_C0402_T02_H28]  134.21 113.85 90 bottom
PC9604  1000PF/50V  [TX_C0402]  137.41 103.76 0 top
PC9605  330PF/50V  [TX_C0402]  134.75 97.14 0 bottom
PC9606  22UF/6.3V  [TX_C0603_T02_H39]  145.67 94.95 270 bottom
PC9607  22UF/6.3V  [TX_C0603_T02_H39]  147.57 104.98 0 bottom
PC9608  22UF/6.3V  [TX_C0603_T02_H39]  147.57 103.63 0 bottom
PC9609  22UF/6.3V  [TX_C0603_T02_H39]  152.5 104.98 0 bottom
PC9610  22UF/6.3V  [TX_C0603_T02_H39]  152.5 103.63 0 bottom
PC9611  22UF/6.3V  [TX_C0603_T02_H39]  143 94.95 270 bottom
PC9612  22UF/6.3V  [TX_C0603_T02_H39]  147.57 99.52 0 bottom
PC9613  22UF/6.3V  [TX_C0603_T02_H39]  147.57 102.24 0 bottom
PC9614  22UF/6.3V  [TX_C0603_T02_H39]  141.63 94.95 270 bottom
PC9615  10UF/25V  [TX_C0805_T02_H57]  117.3 111.41 90 bottom
PC9616  10UF/25V  [TX_C0805_T02_H57]  119.09 111.41 90 bottom
PC9617  22UF/6.3V  [TX_C0603_T02_H39]  147.57 96.83 0 bottom
PC9618  22UF/6.3V  [TX_C0603_T02_H39]  149.86 104.98 180 bottom
PC9619  22UF/6.3V  [TX_C0603_T02_H39]  147.02 94.95 270 bottom
PC9620  22UF/6.3V  [TX_C0603_T02_H39]  149.86 103.63 180 bottom
PC9621  22UF/6.3V  [TX_C0603_T02_H39]  147.56 98.17 0 bottom
PC9622  22UF/6.3V  [TX_C0603_T02_H39]  147.57 100.89 0 bottom
PC9623  22UF/6.3V  [TX_C0603_T02_H39]  144.32 94.95 270 bottom
PC9624  820PF/50V  [TX_C0402]  118.47 107.34 90 bottom
PC9625  1000PF/50V  [TX_C0402]  128.93 110.29 270 top
PC9626  10UF/6.3V  [TX_C0402_T02_H28]  135.26 113.85 90 bottom
PC9627  1000PF/50V  [TX_C0402]  125.37 104.93 180 bottom
PC9800  0.1UF/25V  [TX_C0402]  198.32 64.92 180 bottom
PC9801  10UF/25V  [TX_C0805_T02_H57]  196.88 67.08 270 bottom
PC9802  10UF/25V  [TX_C0805_T02_H57]  195.1 67.08 270 bottom
PC9803  0.1UF/25V  [TX_C0402]  198.53 69.12 90 bottom
PC9804  0.22uF/25V  [TX_C0402_H22]  191.74 66.65 180 top
PC9805  22UF/6.3V  [TX_C0603_T02_H39]  176.94 66.55 270 bottom
PC9806  22UF/6.3V  [TX_C0603_T02_H39]  178.59 66.55 270 bottom
PC9807  22UF/6.3V  [TX_C0603_T02_H39]  180.24 66.55 270 bottom
PC9808  2.2UF/10V  [TX_C0402]  191.41 70.26 90 top
PC9809  1000PF/50V  [TX_C0402]  191.36 63.71 270 top
PC9811  1UF/16V  [TX_C0402]  34.77 72.62 0 top
PCE7900  15UF/25V  [TX_C3528_T02_H79]  155.22 31.9 270 bottom
PCE8000  15UF/25V  [TX_C3528_T02_H79]  158.47 59.38 180 bottom
PCE8100  330UF/2V  [TX_C7343D_T02_H83]  144.2 53.57 180 bottom
PCE8600  220UF/2V  [TX_C7343D_299X177]  97.87 106.1 180 bottom
PCE8601  1PS79SB30  [TX_SOD523_1D7_H28]  105.23 90.9 90 top
PCE8900  15UF/25V  [TX_C3528_T02_H79]  183.87 33.56 0 bottom
PCE8901  100UF/6.3V  [TX_C7343D_T02_H83]  191.67 46.56 0 bottom
PCE8902  100UF/6.3V  [TX_C7343D_T02_H83]  185.74 60.8 180 bottom
PCE9600  330UF/2V  [TX_C7343D_T02_H83]  148.01 110.31 270 bottom
PCE9601  330UF/2V  [TX_C7343D_T02_H83]  152.91 110.31 270 bottom
PCE9602  330UF/2V  [TX_C7343D_T02_H83]  141.1 112.32 180 bottom
PD7600  CH14PT  [TX_SMA_181X110]  48.11 107.2 90 bottom
PD7601  BAV99W  [TX_SOT323_T01X02]  17.76 51.69 180 bottom
PD7602  AZ5725-01F  [TX_ESD_2P_33_39X24_COLAY]  45.87 95.54 0 top
PD7700  1SS400  [TX_SOD523_1D7_T01_H26]  196.19 32.2 180 top
PD7701  1SS400  [TX_SOD523_1D7_T01_H26]  196.19 33.45 180 top
PD8800  CH751H-40AGP  [TX_SOD323_H39]  47.6 12.47 270 top
PD9400  1.2V/0.1A  [TX_SOD323F_H49]  117.12 106.02 270 bottom
PD9800  1.2V/0.1A  [TX_SOD323F_H49]  192.56 62.07 180 bottom
PJP7700  SHORT_PIN  [NB_PWR_FB_SHORT_PT]  186.21 29.82 90 bottom
PJP7701  SHORT_PIN  [NB_PWR_FB_SHORT_PT]  186.21 30.58 270 bottom
PJP7702  SHORT_PIN  [NB_PWR_FB_SHORT_PT]  153.47 27.14 90 bottom
PJP7703  SHORT_PIN  [NB_PWR_FB_SHORT_PT]  153.47 26.33 270 bottom
PJP7900  SHORT_PIN_6X20  [TV_RTC_SHORT_6X20]  162.69 32.39 270 bottom
PJP7901  SHORT_PIN_6X20  [TV_RTC_SHORT_6X20]  145.95 47.73 0 bottom
PJP7902  SHORT_PIN_6X20  [TV_RTC_SHORT_6X20]  142.44 47.73 180 bottom
PJP7903  SHORT_PIN_6X20  [TV_RTC_SHORT_6X20]  145.34 61.83 0 bottom
PJP7904  SHORT_PIN_6X20  [TV_RTC_SHORT_6X20]  141.81 61.5 180 bottom
PJP8000  SHORT_PIN_6X20  [TV_RTC_SHORT_6X20]  147.55 37.11 0 bottom
PJP8001  SHORT_PIN_6X20  [TV_RTC_SHORT_6X20]  144.04 37.24 180 bottom
PJP8002  SHORT_PIN_6X20  [TV_RTC_SHORT_6X20]  145.75 70.26 0 bottom
PJP8003  SHORT_PIN_6X20  [TV_RTC_SHORT_6X20]  142.24 70.26 180 bottom
PJP8600  SHORT_PIN  [NB_PWR_FB_SHORT_PT]  95.71 106.1 180 bottom
PJP8601  3MM_OPEN_5MIL  [3MM_OPEN_5MIL_M1M2]  94.98 98.35 90 bottom
PJP8602  0Ohm  [TX_R0402_SHORT]  97.76 91.85 180 bottom
PJP8700  SHORT_PIN  [NB_PWR_FB_SHORT_PT]  164.11 48.57 0 bottom
PJP8701  2MM_OPEN_5MIL  [2MM_OPEN_5MIL_M1M2]  165.07 52.81 180 bottom
PJP8800  SHORT_PIN  [NB_PWR_FB_SHORT_PT]  49.05 18.24 270 bottom
PJP8801  SHORT_PIN  [NB_PWR_FB_SHORT_PT]  99.97 111.69 180 bottom
PJP8802  1MM_OPEN_M1M2  [1MM_OPEN_5MIL_M1M2]  50.5 16.23 180 bottom
PJP8900  SHORT_PIN  [NB_PWR_FB_SHORT_PT]  194.95 48.01 90 bottom
PJP8901  SHORT_PIN  [NB_PWR_FB_SHORT_PT]  183.63 60.81 0 bottom
PJP8902  3MM_OPEN_5MIL  [3MM_OPEN_5MIL_M1M2]  198.7 46.19 0 bottom
PJP8903  3MM_OPEN_5MIL  [3MM_OPEN_5MIL_M1M2]  179.13 62.26 90 bottom
PJP9500  1MM_OPEN_M1M2  [1MM_OPEN_5MIL_M1M2]  166.78 62.87 270 bottom
PJP9501  1MM_OPEN_M1M2  [1MM_OPEN_5MIL_M1M2]  159.54 69.4 270 bottom
PJP9502  SHORT_PIN  [NB_PWR_FB_SHORT_PT]  161.42 71.88 90 bottom
PJP9503  1MM_OPEN_M1M2  [1MM_OPEN_5MIL_M1M2]  182.65 113.06 270 bottom
PJP9504  2MM_OPEN_5MIL  [2MM_OPEN_5MIL_M1M2]  163.4 107.57 270 bottom
PJP9505  SHORT_PIN  [NB_PWR_FB_SHORT_PT]  167.74 110.49 90 bottom
PJP9600  SHORT_PIN  [NB_PWR_FB_SHORT_PT]  137.6 103.2 0 bottom
PJP9601  SHORT_PIN  [NB_PWR_FB_SHORT_PT]  141.08 103.13 180 bottom
PJP9602  SHORT_PIN  [NB_PWR_FB_SHORT_PT]  129.82 109.45 0 bottom
PJP9603  SHORT_PIN  [NB_PWR_FB_SHORT_PT]  133.2 109.43 180 bottom
PJP9800  3MM_OPEN_5MIL  [3MM_OPEN_5MIL_M1M2]  178.53 69.44 0 bottom
PJP9801  SHORT_PIN  [NB_PWR_FB_SHORT_PT]  176.3 67.21 180 bottom
PL7600  70Ohm/100Mhz  [TX_L0603_T015]  43.43 101.75 90 top
PL7601  70Ohm/100Mhz  [TX_L0603_T015]  45.97 101.7 90 top
PL7602  70Ohm/100Mhz  [TX_L0603_T015]  53.87 102.47 0 top
PL7603  70Ohm/100Mhz  [TX_L0603_T015]  35.97 99.29 90 top
PL7604  70Ohm/100Mhz  [TX_L0603_T015]  34.57 99.29 90 top
PL7605  600ohm/100Mhz  [TX_L0402_H24]  45.87 96.57 0 top
PL7606  70Ohm/100Mhz  [TX_L0603_T015]  32.94 100.21 90 top
PL7700  2.2UH  [TX_INDUCTOR_2P_S260_CYN_T02]  173.56 24.82 180 bottom
PL7900  0.15uH  [TX_INDUCTOR_2P_278X260_H118]  144.2 47.73 180 bottom
PL7901  0.15uH  [TX_INDUCTOR_2P_278X260_H118]  143.56 62.13 180 bottom
PL8000  0.47uH  [TX_INDUCTOR_2P_274X260_CYN]  145.8 37.24 180 bottom
PL8001  0.15uH  [TX_INDUCTOR_2P_278X260_H118]  143.99 70.26 180 bottom
PL8600  1UH  [TX_INDUCTOR_2P_S268_MI_COLA]  88.72 105.88 0 bottom
PL8700  1UH  [TX_INDUCTOR_2P_S268_MI_COLA]  165.33 41.57 180 bottom
PL8800  2.2uH  [TX_INDUCTOR_2P_98X79_TA_H47]  46.63 19.03 0 bottom
PL8801  2.2uH  [TX_INDUCTOR_2P_98X79_TA_H47]  103.2 112.17 180 bottom
PL8900  3.3UH  [TX_INDUCTOR_2P_S406]  194.69 38.97 0 bottom
PL8901  3.3uH  [TX_INDUCTO_2P_287X268_COLAY]  184.02 54.87 180 bottom
PL9500  2.2uH  [TX_INDUCTOR_2P_98X79_TA_H47]  162.97 69.5 180 bottom
PL9501  1.0uH  [TX_INDUCTOR_2P_106X87]  169.29 108.38 180 bottom
PL9600  0.15uH  [TX_INDUCTOR_2P_278X260_H118]  139.32 103.13 0 bottom
PL9601  0.15uH  [TX_INDUCTOR_2P_278X260_H118]  131.47 109.2 0 bottom
PL9800  1UH  [TX_INDUCTOR_2P_S268_MI_COLA]  185.7 66.8 180 bottom
PQ7600  SI7121DN-T1-GE3  [TX_SI7501DN_H44]  46.16 108.63 270 top
PQ7601  UM6K1N  [TX_SC70_S6_H47]  20.55 55.35 0 bottom
PQ7602  PMBS3904  [TX_SOT23_2D4_H43]  17.45 55.4 90 bottom
PQ7603  UM6K1N  [TX_SC70_S6_H47]  65.84 98.71 180 top
PQ7605  BC846BPN  [TX_SOT363_PHILIPS]  70.94 106.02 270 top
PQ7606  BC856BS  [TX_SOT363_PHILIPS]  70.94 108.66 270 top
PQ7607  SI7121DN-T1-GE3  [TX_SI7501DN_H44]  52.73 108.77 90 top
PQ7608  UM6K1N  [TX_SC70_S6_H47]  30.07 103.6 90 top
PQ7609  BC846BPN  [TX_SOT363_PHILIPS]  64.97 107.37 90 top
PQ7610  BC846BPN  [TX_SOT363_PHILIPS]  34.25 109.55 270 top
PQ7611  BC856BS  [TX_SOT363_PHILIPS]  30.07 107.78 0 top
PQ7612  UM6K1N  [TX_SC70_S6_H47]  33.96 107.13 270 top
PQ7613  SI7121DN-T1-GE3  [TX_SI7501DN_H44]  37.72 105.31 0 top
PQ7614  SI7121DN-T1-GE3  [TX_SI7501DN_H44]  41.28 107.05 180 top
PQ7700  SIRA14DP-T1-GE3  [TX_SI7850DP]  181.13 23.88 0 bottom
PQ7701  SI7121DN-T1-GE3  [TX_SI7501DN_H44]  147.3 25.86 270 bottom
PQ7702  SISA14DN-T1-GE3  [TX_SI7501DN_H44]  180.49 28.76 0 bottom
PQ7703  SISA14DN-T1-GE3  [TX_SI7501DN_H44]  163.61 27.56 180 bottom
PQ7704  SISA14DN-T1-GE3  [TX_SI7501DN_H44]  167.11 26.47 180 bottom
PQ7900  FDPC5018SG  [TX_POWER_8P_50_2PAD_8V]  152.33 47.91 270 bottom
PQ7901  FDPC5018SG  [TX_POWER_8P_50_2PAD_8V]  151.54 62.03 270 bottom
PQ8000  SIZ340DT-T1-GE3  [TX_POWERPAIR_8P_2PAD_VISHAY]  152.78 37.62 0 bottom
PQ8001  FDPC5018SG  [TX_POWER_8P_50_2PAD_8V]  151.89 71.55 270 bottom
PQ8600  SIZ340DT-T1-GE3  [TX_POWERPAIR_8P_2PAD_VISHAY]  82.32 107.47 180 bottom
PQ8900  SIZ340DT-T1-GE3  [TX_POWERPAIR_8P_2PAD_VISHAY]  183.4 42.17 180 bottom
PQ8901  SIZ340DT-T1-GE3  [TX_POWERPAIR_8P_2PAD_VISHAY]  191.41 54.24 180 bottom
PQ9600  FDPC5018SG  [TX_POWER_8P_50_2PAD_8V]  131.19 100.31 90 bottom
PQ9601  FDPC5018SG  [TX_POWER_8P_50_2PAD_8V]  123.44 108.49 90 bottom
PR7600  100Ohm  [TX_R0603_H24]  47.8 102.62 180 bottom
PR7601  1KOhm  [TX_R0402]  69.57 110.44 180 top
PR7602  100Ohm  [TX_R0603_H24]  46.03 102.34 90 bottom
PR7603  100Ohm  [TX_R0603_H24]  45.92 110.37 180 bottom
PR7604  100Ohm  [TX_R0603_H24]  45.72 108.46 270 bottom
PR7607  100Ohm  [TX_R0402]  20.6 52.1 180 bottom
PR7608  100KOhm  [TX_R0402]  16.21 58.19 0 bottom
PR7609  10KOhm  [TX_R0402]  20.6 53.04 0 bottom
PR7610  15KOhm  [TX_R0402]  17.83 58.19 0 bottom
PR7611  470KOhm  [TX_R0402]  37.62 89.51 270 top
PR7612  71.5KOhm  [TX_R0402]  36.6 89.51 90 top
PR7613  100KOhm  [TX_R0402]  36.35 85.17 0 top
PR7614  0Ohm  [TX_R0402_0OHM]  38.3 86.11 90 top
PR7615  1MOhm  [TX_R0402]  66.27 101.68 0 top
PR7616  1MOhm  [TX_R0402]  68.15 101.68 0 top
PR7617  10KOhm  [TX_R0402]  67.92 97.59 90 top
PR7618  100KOhm  [TX_R0402]  69.82 97.59 90 top
PR7619  2.2kOHM  [TX_R0402]  20.6 51.16 180 bottom
PR7620  100KOhm  [TX_R0402]  73.63 105.69 90 top
PR7621  100KOhm  [TX_R0402]  73.63 107.3 90 top
PR7622  49.9KOhm  [TX_R0402]  73.23 110.44 180 top
PR7623  100KOhm  [TX_R0402]  74.85 110.44 0 top
PR7624  220KOhm  [TX_R0402]  73.63 108.92 90 top
PR7625  240KOhm  [TX_R0402]  56.4 109.12 90 top
PR7626  47KOhm  [TX_R0402]  55.96 110.42 180 top
PR7627  47KOhm  [TX_R0402]  67.92 107.27 180 top
PR7628  47KOhm  [TX_R0402]  62.38 106.89 90 top
PR7629  2.2Ohm  [TX_R0805_H26]  33.58 102.39 180 top
PR7633  100KOhm  [TX_R0402]  34.39 105.23 90 top
PR7634  680KOhm  [TX_R0402]  38.25 100.93 0 top
PR7635  10KOhm  [TX_R0402]  32.69 105.26 90 top
PR7636  100KOhm  [TX_R0402]  36.82 108.33 90 top
PR7637  100KOhm  [TX_R0402]  37.26 109.76 0 top
PR7638  100KOhm  [TX_R0402]  28.65 105.18 180 top
PR7639  49.9KOhm  [TX_R0402]  30.28 105.21 180 top
PR7640  220KOhm  [TX_R0402]  31.69 108.59 270 top
PR7641  1KOhm  [TX_R0402]  28.32 106.45 270 top
PR7643  100Ohm  [TX_R0402]  66.9 109.25 0 top
PR7644  0Ohm  [TX_R0402_0OHM]  30.73 99.44 180 top
PR7645  100KOhm  [TX_R0402]  38.79 108 180 top
PR7646  100KOhm  [TX_R0402]  71.59 110.44 0 top
PR7700  20mOhm  [TX_R1508_H35]  186.18 30.18 270 bottom
PR7701  0Ohm  [TX_R0603_0OHM_H24]  197.1 21.54 0 bottom
PR7702  100KOhm  [TX_R0402]  200.69 32.15 180 bottom
PR7703  2.2Ohm  [TX_R0402]  189.26 30.43 0 bottom
PR7704  2.2Ohm  [TX_R0402]  189.28 29.16 270 bottom
PR7705  4.7Ohm  [TX_R0603_H24]  195.96 29.62 180 top
PR7706  100KOhm  [TX_R0402]  198.04 29.62 0 top
PR7707  402KOhm  [TX_R0402]  194.74 31.22 0 bottom
PR7708  10Ohm  [TX_R0603_H24]  192.48 31.37 180 bottom
PR7709  150KOhm  [TX_R0402]  200.69 31.22 0 bottom
PR7710  100KOhm  [TX_R0402]  196.37 31.22 0 bottom
PR7711  0Ohm  [TX_R0402_0OHM]  198.48 23.83 0 top
PR7712  10mOhm  [TX_R1508_H35]  153.49 26.75 270 bottom
PR7713  1Ohm  [TX_R0402]  153.09 29.24 270 bottom
PR7714  1Ohm  [TX_R0402]  150.72 27.79 270 bottom
PR7715  1KOhm  [TX_R0402]  200.36 24.71 0 bottom
PR7716  147KOhm  [TX_R0402]  200.71 28.44 0 bottom
PR7717  698Ohm  [R0402]  200.71 27.47 0 bottom
PR7718  0Ohm  [TX_R0603_0OHM_H24]  183.03 27.84 270 bottom
PR7719  0Ohm  [TX_R0402_0OHM]  200.15 23.79 0 bottom
PR7720  0Ohm  [TX_R0402_0OHM]  196.41 29.47 90 bottom
PR7721  0Ohm  [TX_R0402_0OHM]  199.16 29.82 90 bottom
PR7722  0Ohm  [TX_R0402_0OHM]  197.33 29.47 90 bottom
PR7723  0Ohm  [TX_R0402_0OHM]  198.25 29.47 90 bottom
PR7724  0Ohm  [TX_R0402_0OHM]  200.74 26.54 0 bottom
PR7725  0Ohm  [TX_R0402_0OHM]  200.36 25.63 0 bottom
PR7726  100KOhm  [TX_R0402]  200.71 30.28 180 bottom
PR7800  4.7KOhm  [TX_R0402]  176.94 57 90 bottom
PR7801  0Ohm  [TX_R0603_SHORT]  168 46.33 270 bottom
PR7802  0Ohm  [TX_R0603_SHORT]  169.7 45.37 270 bottom
PR7803  11KOhm  [TX_R0402]  176.53 55.69 0 bottom
PR7804  1KOhm  [TX_R0402]  178.59 52.79 180 bottom
PR7805  4.7KOhm  [TX_R0402]  145.09 66.6 270 top
PR7806  549OHM  [TX_R0402]  178.59 53.72 180 bottom
PR7807  11KOhm  [TX_R0402]  180.37 45.72 0 top
PR7808  0Ohm  [TX_R0402_0OHM]  178.44 56.47 270 top
PR7809  2.43KOhm  [TX_R0402]  178.46 45.87 0 top
PR7810  412Ohm  [TX_R0402]  178.16 44.6 270 top
PR7811  0Ohm  [TX_R0402_0OHM]  177.04 56.39 270 top
PR7812  1.3KOhm  [TX_R0402]  173.47 56.19 180 bottom
PR7813  1.82KOhm  [TX_R0402]  179.35 50.29 0 bottom
PR7814  1KOhm  [TX_R0402]  176.15 58.27 180 bottom
PR7815  2KOhm  [TX_R0402]  174.19 53.57 90 bottom
PR7816  2.15KOHM  [TX_R0402]  180.31 47.53 0 bottom
PR7817  0Ohm  [TX_R0402_0OHM]  182.37 47.96 90 bottom
PR7819  0Ohm  [TX_R0402_0OHM]  174.04 56.64 90 top
PR7820  1.78KOhm  [TX_R0402]  174.78 59.36 270 bottom
PR7821  499Ohm  [TX_R0402]  180.03 46.59 0 bottom
PR7822  2KOhm  [TX_R0402]  180.11 48.45 0 bottom
PR7823  100Ohm  [TX_R0402]  175.31 53.24 90 top
PR7824  105KOhm  [TX_R0402]  172.97 55.55 270 top
PR7825  97.6KOHM  [TX_R0402]  176.71 48.84 180 top
PR7826  16.9KOhm  [TX_R0402]  177.24 47.58 270 top
PR7827  2.61KOhm  [TX_R0402]  165 45.57 180 top
PR7828  16.9KOhm  [TX_R0402]  173.89 53.47 270 top
PR7829  100KOHM  [TX_R0402_H24]  156.34 46.59 270 bottom
PR7830  100KOHM  [TX_R0402_H24]  159.87 61.52 0 bottom
PR7831  11KOhm  [TX_R0402]  166.29 46.28 90 top
PR7832  100KOhm  [TX_R0402]  170.61 47.27 180 top
PR7833  9.31KOhm  [TX_R0402]  170.46 46.33 180 top
PR7834  100Ohm  [TX_R0402]  170.22 49.56 180 bottom
PR7835  487Ohm  [TX_R0402]  170.87 44.17 90 top
PR7836  0Ohm  [TX_R0402_SHORT]  170.51 50.5 180 bottom
PR7837  0Ohm  [TX_R0402_0OHM]  170.51 51.46 180 bottom
PR7838  1KOhm  [TX_R0402]  170.99 42.9 0 top
PR7839  10OHM  [TX_R0402]  170.61 48.21 180 top
PR7840  0Ohm  [TX_R0402_SHORT]  169.8 49.43 180 top
PR7842  2.7KOhm  [TX_R0402]  176.3 43.72 90 top
PR7843  51Ohm  [TX_R0402]  170.59 50.45 180 top
PR7844  0Ohm  [TX_R0402_0OHM]  165.02 47.58 180 top
PR7845  2.15KOHM  [TX_R0402]  173.43 42.22 90 top
PR7846  45.3Ohm  [TX_R0402]  167.44 50.93 180 top
PR7847  100Ohm  [TX_R0402]  168.22 48.03 180 top
PR7848  301Ohm  [TX_R0402]  174.4 42.22 90 top
PR7849  110KOHM  [TX_R0402]  178.23 44.6 90 bottom
PR7850  0Ohm  [TX_R0402_0OHM]  171.86 50.83 270 top
PR7851  2KOhm  [TX_R0402]  174.11 43.97 90 bottom
PR7853  453Ohm  [TX_R0402]  178.51 54.08 90 top
PR7854  4.3KOHM  [TX_R0402]  173.47 55.25 180 bottom
PR7855  3.57KOhm  [TX_R0402]  173.84 59.36 270 bottom
PR7856  93.1KOHM  [TX_R0402]  172.29 53.01 180 top
PR7900  0Ohm  [TX_R0805_0OHM_H26]  159.16 49.81 180 bottom
PR7902  0Ohm  [TX_R0805_0OHM_H26]  158.75 47.58 180 bottom
PR7903  4.7OHM  [TX_R1206_H30]  148.01 42.75 0 bottom
PR7904  3.65KOhm  [TX_R0402]  144.63 43.33 270 bottom
PR7905  2.2Ohm  [TX_R0402]  143.71 43.33 270 bottom
PR7906  100KOhm  [TX_R0402]  145.54 43.33 270 bottom
PR7907  0Ohm  [TX_R0805_0OHM_H26]  158.19 62.5 90 bottom
PR7908  0Ohm  [TX_R0805_0OHM_H26]  159.49 56.85 180 bottom
PR7909  4.7OHM  [TX_R1206_H30]  148.26 57.2 0 bottom
PR7910  3.65KOhm  [TX_R0402]  144.88 57.46 270 bottom
PR7911  100KOhm  [TX_R0402]  145.82 57.46 270 bottom
PR7912  2.2Ohm  [TX_R0402]  143.41 58.07 0 bottom
PR7913  8.2KOhm  [TX_R0402]  157.28 49.3 270 bottom
PR7914  0Ohm  [TX_R0805_0OHM_H26]  148.59 49.33 0 top
PR7915  8.2KOhm  [TX_R0402]  155.53 63.07 270 bottom
PR7916  0Ohm  [TX_R0805_0OHM_H26]  147.98 62.16 90 top
PR7917  0Ohm  [TX_R0402_0OHM]  159.03 42.88 0 bottom
PR7918  0Ohm  [TX_R0402_0OHM]  160.81 48.14 270 bottom
PR7919  0Ohm  [TX_R0402_0OHM]  159.41 52.22 0 bottom
PR7920  0Ohm  [TX_R0402_0OHM]  161.42 57.05 270 bottom
PR7921  100KOhm  [TX_R0402]  142.77 43.33 270 bottom
PR7922  100KOhm  [TX_R0402]  142.11 57.71 270 bottom
PR8000  0Ohm  [TX_R0805_0OHM_H26]  149.73 31.85 90 bottom
PR8001  0Ohm  [TX_R0805_0OHM_H26]  151.51 37.11 90 top
PR8002  8.2KOhm  [TX_R0402]  149.66 38.2 180 top
PR8003  0Ohm  [TX_R0805_0OHM_H26]  151.44 32.06 90 bottom
PR8004  3.65KOhm  [TX_R0402]  145.82 32.82 270 bottom
PR8005  2.2Ohm  [TX_R0402]  144.91 32.82 270 bottom
PR8006  0Ohm  [TX_R0805_0OHM_H26]  158.18 72.52 90 bottom
PR8007  0Ohm  [TX_R0805_0OHM_H26]  159.51 67.13 180 bottom
PR8008  4.7OHM  [TX_R1206_H30]  148.51 69.04 90 top
PR8009  3.65KOhm  [TX_R0402]  144.15 67.46 270 top
PR8010  2.2Ohm  [TX_R0402]  143.21 67.46 270 top
PR8011  8.2KOhm  [TX_R0402]  156.85 73.36 270 bottom
PR8012  0Ohm  [TX_R0805_0OHM_H26]  147.29 73.13 0 top
PR8013  0Ohm  [TX_R0402_0OHM]  142.98 29.72 0 bottom
PR8014  0Ohm  [TX_R0402_0OHM]  148.94 29.61 180 bottom
PR8015  0Ohm  [TX_R0402_0OHM]  159.84 62.59 0 bottom
PR8016  0Ohm  [TX_R0402_0OHM]  161.55 67.2 270 bottom
PR8600  2.2Ohm  [TX_R0603_H24]  102.24 100.82 270 top
PR8601  0Ohm  [TX_R0805_0OHM_H26]  96.42 98.05 180 top
PR8602  909KOHM  [TX_R0402]  104.29 98.53 180 top
PR8603  0Ohm  [TX_R0402_SHORT]  106.32 95.4 180 top
PR8604  200Ohm  [TX_R0402]  106.32 94.47 180 top
PR8605  8.2KOhm  [TX_R0402]  83.06 103.53 0 top
PR8606  10KOhm  [TX_R0402]  104.29 97.59 0 top
PR8607  4.7OHM  [TX_R1206_H30]  86.49 111.39 180 bottom
PR8608  8.2KOhm  [TX_R0402]  82.4 109.71 180 top
PR8609  6.2KOHM  [TX_R0402]  101.96 94.41 270 top
PR8610  10KOhm  [TX_R0402]  104.17 94.97 0 top
PR8611  226KOhm  [TX_R0402]  100.15 100.99 270 top
PR8612  0Ohm  [TX_R0402_SHORT]  99.57 94.52 180 top
PR8613  0Ohm  [TX_R0603_SHORT]  79.81 102.72 180 bottom
PR8614  0Ohm  [TX_R0402_SHORT]  106.35 97.59 180 top
PR8615  0Ohm  [TX_R0402_0OHM]  103.77 90.64 90 top
PR8616  10KOhm  [TX_R0402]  102.8 90.6 90 top
PR8617  0Ohm  [TX_R0805_0OHM_H26]  80.79 103.4 0 top
PR8618  0Ohm  [TX_R0805_0OHM_H26]  81.78 107.39 0 top
PR8700  0Ohm  [TX_R0603_SHORT]  183.01 36.03 180 bottom
PR8701  0Ohm  [TX_R0402_0OHM]  174.15 41.38 270 bottom
PR8702  0Ohm  [TX_R0402_SHORT]  173.23 41.38 270 bottom
PR8703  4.7Ohm  [TX_R0603_H24]  171.76 40.82 270 bottom
PR8704  2.2Ohm  [TX_R0805_H26]  170.41 38.8 180 bottom
PR8705  100KOhm  [TX_R0402]  174.09 39.12 0 bottom
PR8706  0Ohm  [TX_R0402_0OHM]  173.63 40.08 180 bottom
PR8707  6.98KOhm  [TX_R0402]  177.62 30.74 180 bottom
PR8708  10KOhm  [TX_R0402]  176.35 31.09 90 bottom
PR8709  523OHM  [TX_R0402]  175.41 30.3 90 bottom
PR8710  1MOhm  [TX_R0402]  172.49 29.47 0 bottom
PR8711  5.1OHM  [TX_R0402]  177.62 32.51 90 bottom
PR8712  0Ohm  [TX_R0402_0OHM]  176.75 39.92 180 bottom
PR8800  1KOhm  [TX_R0402]  48.79 20.4 90 bottom
PR8801  0Ohm  [TX_R0603_SHORT]  40.77 20.78 0 top
PR8802  51KOhm  [TX_R0402]  39.32 18 90 top
PR8803  162KOhm  [TX_R0402]  40.26 18 90 top
PR8804  33KOHM  [TX_R0402]  40.87 16.72 180 top
PR8805  33KOHM  [TX_R0402]  109.27 114.25 180 top
PR8806  0Ohm  [TX_R0603_SHORT]  97.51 111.84 180 bottom
PR8807  102KOhm  [TX_R0402]  110.82 111.91 0 top
PR8808  0Ohm  [TX_R0603_SHORT]  111.81 109.43 180 bottom
PR8809  1KOhm  [TX_R0402]  99.8 113.87 90 bottom
PR8810  51KOhm  [TX_R0402]  111.35 114.25 0 top
PR8811  0Ohm  [TX_R0402_SHORT]  108.79 114.3 180 bottom
PR8812  100Ohm  [TX_R0402]  46.41 13.19 270 top
PR8813  330KOHM  [TX_R0402]  46.41 11.53 90 top
PR8814  330KOHM  [TX_R0402]  42.98 13.62 270 top
PR8900  2.2Ohm  [TX_R0603_H24]  196.05 60.1 0 top
PR8901  0Ohm  [VX_R0805_SMALL_SHORT]  178.33 38.13 270 bottom
PR8902  2.2Ohm  [TX_R0805_H26]  204.7 61.23 0 bottom
PR8903  0Ohm  [TX_R0805_0OHM_H26]  185.47 39.3 0 bottom
PR8904  8.2KOhm  [TX_R0402]  185.67 41.1 90 bottom
PR8905  0Ohm  [TX_R0805_0OHM_H26]  183.67 47.58 270 bottom
PR8906  8.2KOhm  [TX_R0402]  183.63 45.58 180 bottom
PR8907  4.7OHM  [TX_R1206_H30]  186.17 44.45 90 bottom
PR8908  1Ohm  [TX_R0603_H24]  203.4 63.33 90 bottom
PR8909  107KOHM  [TX_R0402]  203.51 56.67 180 bottom
PR8910  15.4KOhm  [TX_R0402]  202.13 55.76 90 bottom
PR8911  10KOhm  [TX_R0402]  203.4 55.35 0 bottom
PR8912  75KOhm  [TX_R0402]  200.03 57.86 180 top
PR8913  0Ohm  [VX_R0805_SMALL_SHORT]  180.11 38.13 270 bottom
PR8914  2.2Ohm  [TX_R0805_H26]  196.37 59.59 180 bottom
PR8915  0Ohm  [TX_R0805_0OHM_H26]  192.53 50.6 90 bottom
PR8916  0Ohm  [VX_R0805_SMALL_SHORT]  181.89 38.15 270 bottom
PR8917  8.2KOhm  [TX_R0402]  194.84 52.73 90 bottom
PR8918  0Ohm  [TX_R0805_0OHM_H26]  193.83 58.3 270 bottom
PR8919  8.2KOhm  [TX_R0402]  194.69 55.81 270 bottom
PR8920  4.7OHM  [TX_R1206_H30]  191.8 58.45 90 bottom
PR8921  6.81KOhm  [TX_R0402]  198.4 55.83 270 bottom
PR8922  10KOhm  [TX_R0402]  197 56.54 180 bottom
PR8923  200Ohm  [TX_R0402]  203.48 58.98 180 bottom
PR9000  0Ohm  [TX_R0402_SHORT]  41.3 69.12 180 top
PR9001  100KOhm  [TX_R0402]  39.22 69.07 0 top
PR9002  0Ohm  [TX_R0603_SHORT]  32.06 68.43 0 top
PR9003  0Ohm  [TX_R0603_SHORT]  32.79 72.67 0 top
PR9004  0Ohm  [TX_R0402_SHORT]  43.79 70.74 180 top
PR9005  100KOhm  [TX_R0402]  41.43 70.16 0 top
PR9100  0Ohm  [TX_R0402_SHORT]  182.19 11.61 90 bottom
PR9101  100KOhm  [TX_R0402]  181.25 11.61 270 bottom
PR9102  0Ohm  [VX_R0805_SMALL_SHORT]  181.09 17.63 270 bottom
PR9103  0Ohm  [TX_R0402_0OHM]  178.08 11.61 90 bottom
PR9104  100KOhm  [TX_R0402]  179.04 11.61 270 bottom
PR9105  0Ohm  [TX_R0402_0OHM]  177.09 17.45 90 bottom
PR9106  0Ohm  [TX_R0402_SHORT]  196.48 54.5 0 bottom
PR9107  100KOhm  [TX_R0402]  196.62 53.56 180 bottom
PR9108  0Ohm  [TX_R0603_SHORT]  204.47 53.39 180 bottom
PR9109  0Ohm  [TX_R0402_SHORT]  196.35 50.8 0 bottom
PR9110  100KOhm  [TX_R0402]  196.37 51.72 180 bottom
PR9111  0Ohm  [VX_R0805_SMALL_SHORT]  202.88 49.71 180 bottom
PR9200  0Ohm  [TX_R0402_SHORT]  143.33 22.33 180 top
PR9201  100KOhm  [TX_R0402]  141.83 21.97 270 top
PR9202  0Ohm  [TX_R0603_SHORT]  135.61 21.67 0 bottom
PR9203  0Ohm  [VX_R0805_SMALL_SHORT]  135.94 25.58 270 top
PR9204  0Ohm  [VX_R0805_SMALL_SHORT]  140.13 25.12 270 top
PR9205  0Ohm  [TX_R0402_SHORT]  142.67 25.86 270 top
PR9206  0Ohm  [VX_R0805_SMALL_SHORT]  134.42 25.78 0 bottom
PR9207  100KOhm  [TX_R0402]  141.76 25.86 90 top
PR9208  0Ohm  [TX_R0603_SHORT]  136.7 26.95 270 bottom
PR9209  0Ohm  [VX_R0805_SMALL_SHORT]  138.07 25.12 270 top
PR9401  10KOhm  [TX_R0402]  108.03 107.77 0 bottom
PR9402  10KOhm  [TX_R0402]  107.52 104.57 0 bottom
PR9403  10KOhm  [TX_R0402]  107.59 106.17 270 bottom
PR9408  4.7Ohm  [TX_R0603_H24]  112.67 107.98 180 bottom
PR9409  2.2Ohm  [TX_R0402]  110.59 107.83 0 bottom
PR9410  2.2Ohm  [TX_R0805_H26]  119.23 100.51 0 bottom
PR9412  10KOhm  [TX_R0402]  105.89 103.36 180 bottom
